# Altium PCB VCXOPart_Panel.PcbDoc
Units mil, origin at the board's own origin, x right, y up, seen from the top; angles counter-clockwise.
Board outline 8500 x 2950 mil, 4 copper layers (Top Layer, GND, VCC, Bottom Layer), stack 61.712 mil thick; 0 components, 0 nets, 52 pads, 0 vias.
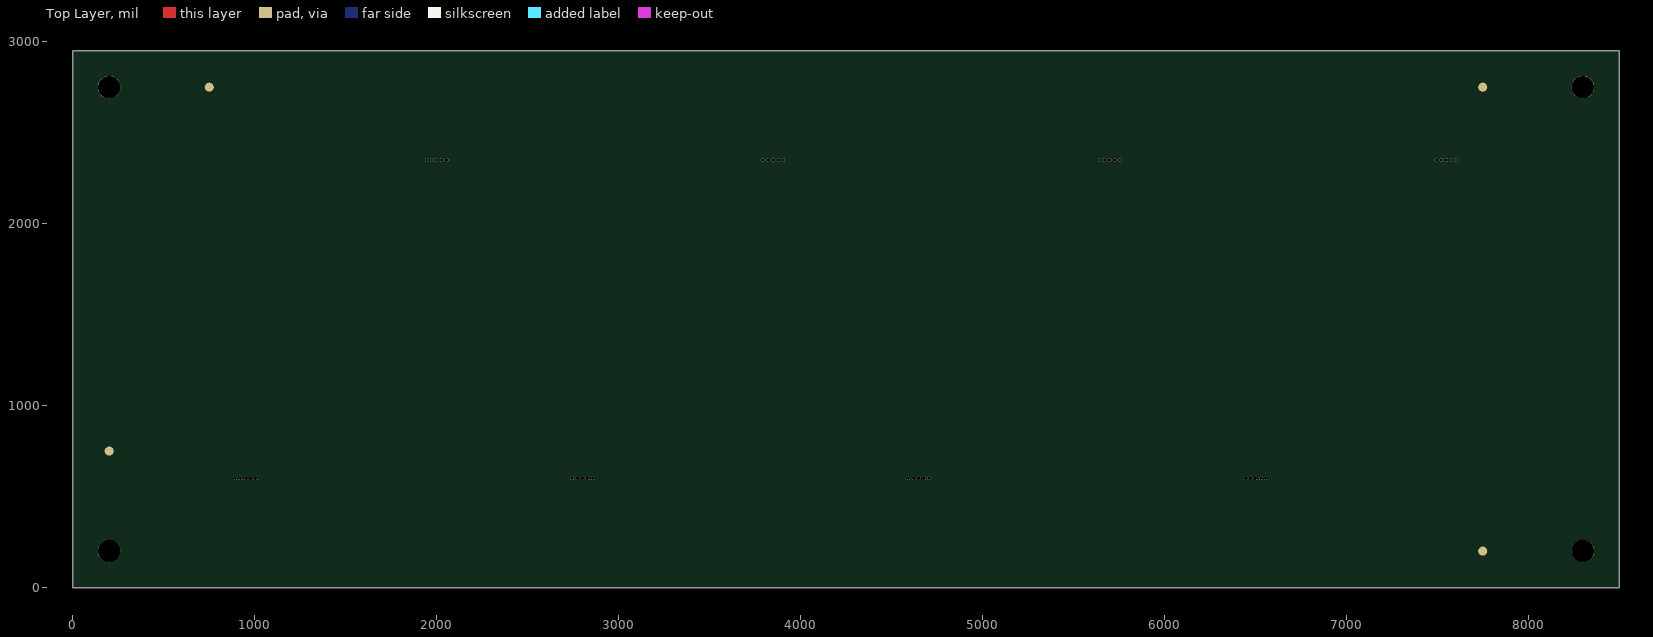
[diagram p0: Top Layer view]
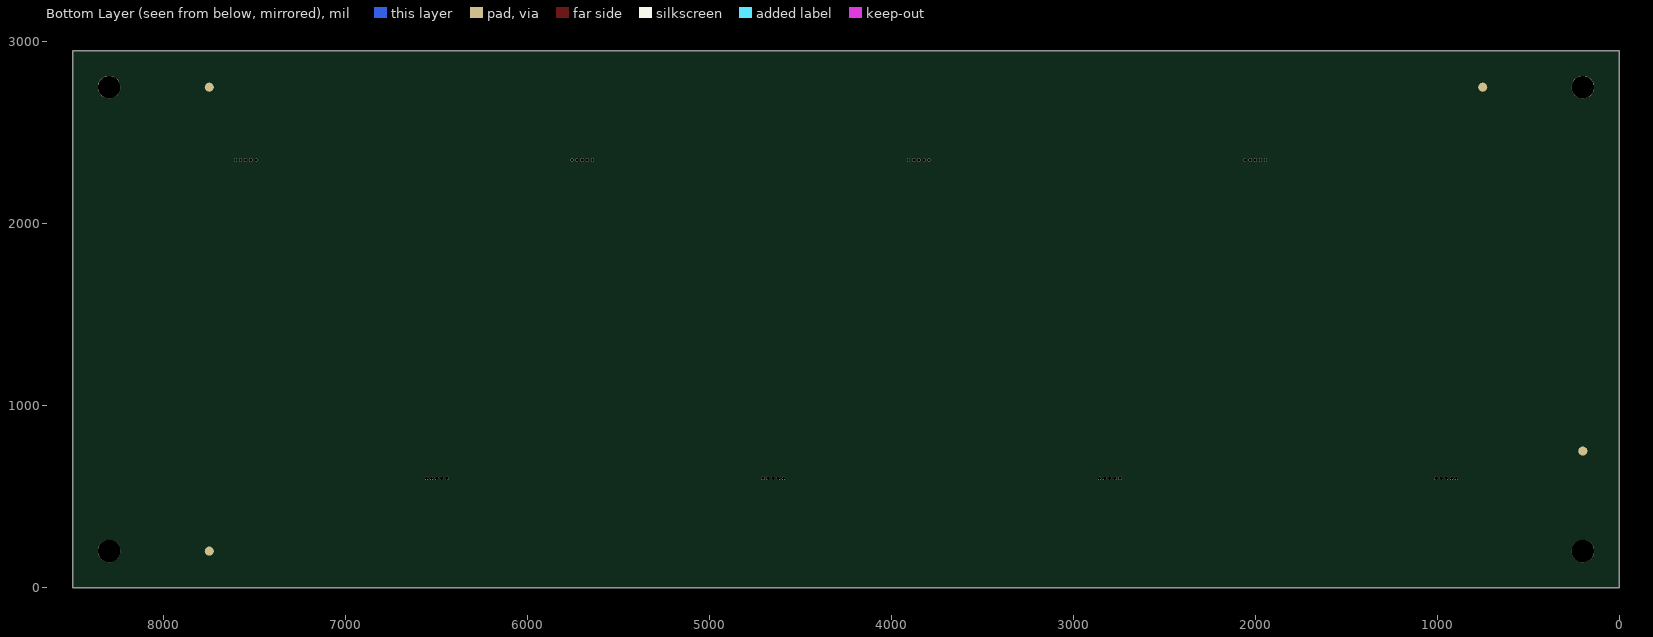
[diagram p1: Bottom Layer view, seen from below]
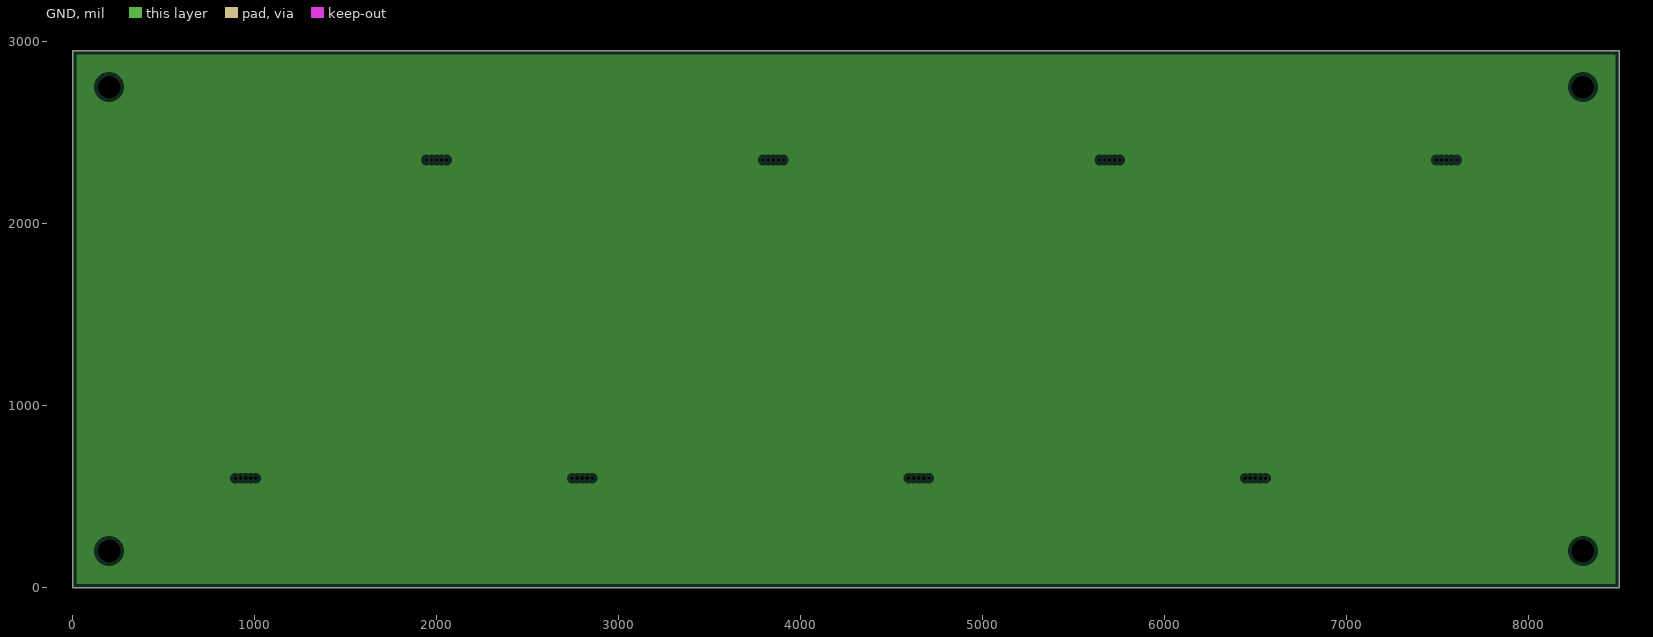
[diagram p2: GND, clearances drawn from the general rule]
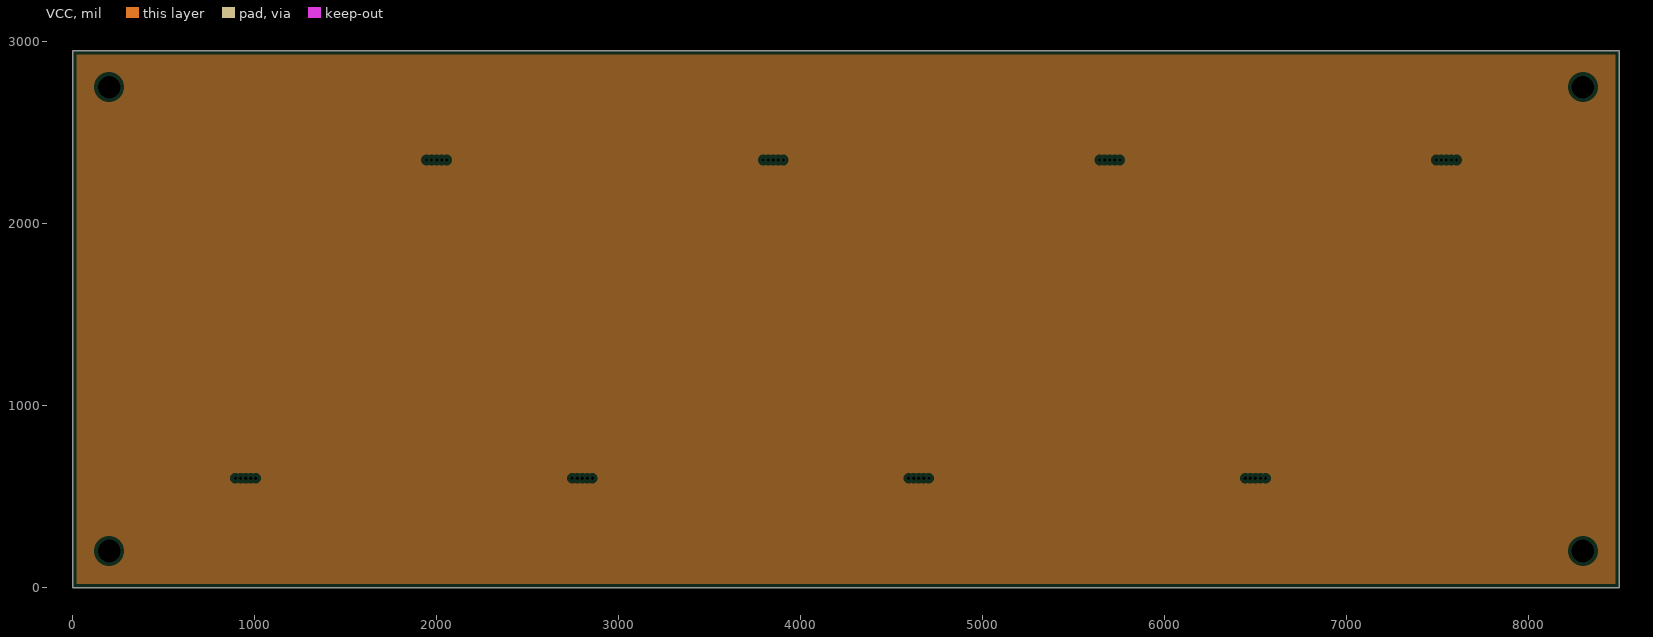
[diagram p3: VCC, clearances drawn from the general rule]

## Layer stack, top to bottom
Top Solder: solder mask 0.4, Solder Resist, Dk 3.5
Top Layer: signal copper 1.378
Dielectric 2: prepreg 8.6, 2116, 2113, Dk 4.3
GND: plane copper 1.378
Dielectric 1: core 39, FR-4, Dk 4.8
VCC: plane copper 1.378
Dielectric 3: prepreg 8.6, 2116, 2113, Dk 4.3
Bottom Layer: signal copper 1.378
Bottom Solder: solder mask 0.4, Solder Resist, Dk 3.5

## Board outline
0,0 0,2950 8500,2950 8500,0

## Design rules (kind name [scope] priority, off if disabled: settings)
Clearance [All] p1: gap=10 ignorepadtopadclearanceinfootprint=FALSE except(0: Arc-Hole Track-Hole SMDPad-Hole THPad-Hole Via-Hole Fill-Hole Poly-Hole Region-Hole Text-Hole)
PlaneClearance [All] p1: clearance=20
PlaneConnect [All] p1: planeconnectstyle=Relief reliefexpansion=20 reliefentries=4 reliefconductorwidth=10 reliefairgap=10
PolygonConnect [All] p1: connectstyle=Relief reliefconductorwidth=10 reliefentries=4 polygonreliefangle="90 Angle" airgapwidth=10
RoutingVias [All] p1: holewidth=28 width=50 viastyle="Through Hole" minholewidth=28 minwidth=50 maxholewidth=28 maxwidth=50
SolderMaskExpansion [All] p1: expansion=4 istentingtop=FALSE
Width [All] p1: maxlimit=10 minlimit=10 preferedwidth=10
28 further rules are at their usual default settings.

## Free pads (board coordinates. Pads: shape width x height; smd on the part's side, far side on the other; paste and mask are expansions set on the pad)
  round 125 hole 125 unplated: 0(200,200) 0(200,2750) 0(8300,200) 0(8300,2750)
  round 50 smd paste-50 mask+50: 0(200,750) 0(750,2750) 0(7750,200) 0(7750,2750)
  round 50 smd far side paste-50 mask+50: 0(200,750) 0(750,2750) 0(7750,200) 0(7750,2750)
  round 18 hole 18 unplated mask+0: 0(894,600) 0(922,600) 0(950,600) 0(978,600) 0(1006,600) 0(1944,2350) 0(1972,2350) 0(2000,2350) 0(2028,2350) 0(2056,2350) 0(2744,600) 0(2772,600) 0(2800,600) 0(2828,600) 0(2856,600) 0(3794,2350) 0(3822,2350) 0(3850,2350) 0(3878,2350) 0(3906,2350) 0(4594,600) 0(4622,600) 0(4650,600) 0(4678,600) 0(4706,600) 0(5644,2350) 0(5672,2350) 0(5700,2350) 0(5728,2350) 0(5756,2350) 0(6444,600) 0(6472,600) 0(6500,600) 0(6528,600) 0(6556,600) 0(7494,2350) 0(7522,2350) 0(7550,2350) 0(7578,2350) 0(7606,2350)

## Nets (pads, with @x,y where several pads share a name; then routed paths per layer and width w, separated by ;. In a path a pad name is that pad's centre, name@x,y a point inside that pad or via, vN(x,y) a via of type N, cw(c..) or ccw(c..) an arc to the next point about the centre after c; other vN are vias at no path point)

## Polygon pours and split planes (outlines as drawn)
no net on GND (split plane): 8479.9,20.1 20.1,20.1 20.1,2929.9 8479.9,2929.9
no net on VCC (split plane): 8479.9,20.1 20.1,20.1 20.1,2929.9 8479.9,2929.9

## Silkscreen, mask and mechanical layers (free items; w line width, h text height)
Mechanical 1:
  the board outline again, w8
Mechanical 2:
  lines w100: 850,550 550,550 550,1325 675,1325 675,1625 550,1625 550,2400 1325,2400 1325,2275 1625,2275 1625,2400 1900,2400 ; 1050,550 1325,550 1325,675 1625,675 1625,550 2700,550 ; 2100,2400 3175,2400 3175,2275 3475,2275 3475,2400 3750,2400 ; 2350,2350 2350,1625 2275,1625 2275,950 2400,950 ; 2400,600 2400,950 ; 2400,2350 2400,1625 2525,1625 2525,1325 2400,1325 2400,950 ; 2900,550 3175,550 3175,675 3475,675 3475,550 4550,550 ; 3950,2400 5025,2400 5025,2275 5325,2275 5325,2400 5600,2400 ; 4200,2350 4200,1625 4125,1625 4125,950 4250,950 ; 4250,600 4250,950 ; 4250,2350 4250,1625 4375,1625 4375,1325 4250,1325 4250,950 ; 4750,550 5025,550 5025,675 5325,675 5325,550 6400,550 ; 5800,2400 6850,2400 ; 6050,2350 6050,1625 5975,1625 5975,950 6100,950 ; 6100,600 6100,950 ; 6100,2350 6100,1625 6225,1625 6225,1325 6100,1325 6100,950 ; 6600,550 6875,550 6875,675 7175,675 7175,550 7950,550 7950,950 7825,950 7825,1625 7900,1625 7900,2400 7650,2400 ; 6875,2400 6875,2275 7175,2275 7175,2400 7450,2400
Mechanical 3:
  drawing of 212 lines, arcs and shapes, not listed
Drill Drawing:
  drawing of 473 lines, arcs and shapes, not listed
  text "Layer" at 70,7539.04 h60
  text "Name" at 479.91,7539.04 h60
  text "Material" at 1409.66,7539.04 h60
  text "Thickness" at 2269.42,7539.04 h60
  text "Constant" at 2919.26,7539.04 h60
  text "Board Layer Stack" at 3489.12,7539.04 h60
  text "Top Overlay" at 479.91,7419.04 h60
  text "Top Solder" at 479.91,7299.04 h60
  text "Solder Resist" at 1409.66,7299.04 h60
  text "0.40mil" at 2269.42,7299.04 h60
  text "3.5" at 2919.26,7299.04 h60
  text "1" at 70,7179.04 h60
  text "Top Layer" at 479.91,7179.04 h60
  text "CF-004" at 1409.66,7179.04 h60
  text "1.38mil" at 2269.42,7179.04 h60
  text "Dielectric 2" at 479.91,7059.04 h60
  text "2116, 2113" at 1409.66,7059.04 h60
  text "8.60mil" at 2269.42,7059.04 h60
  text "4.3" at 2919.26,7059.04 h60
  text "2" at 70,6939.04 h60
  text "GND" at 479.91,6939.04 h60
  text "CF-004" at 1409.66,6939.04 h60
  text "1.38mil" at 2269.42,6939.04 h60
  text "Dielectric 1" at 479.91,6819.04 h60
  text "FR-4" at 1409.66,6819.04 h60
  text "39.00mil" at 2269.42,6819.04 h60
  text "4.8" at 2919.26,6819.04 h60
  text "3" at 70,6699.04 h60
  text "VCC" at 479.91,6699.04 h60
  text "CF-004" at 1409.66,6699.04 h60
  text "1.38mil" at 2269.42,6699.04 h60
  text "Dielectric 3" at 479.91,6579.04 h60
  text "2116, 2113" at 1409.66,6579.04 h60
  text "8.60mil" at 2269.42,6579.04 h60
  text "4.3" at 2919.26,6579.04 h60
  text "4" at 70,6459.04 h60
  text "Bottom Layer" at 479.91,6459.04 h60
  text "CF-004" at 1409.66,6459.04 h60
  text "1.38mil" at 2269.42,6459.04 h60
  text "Bottom Solder" at 479.91,6339.04 h60
  text "Solder Resist" at 1409.66,6339.04 h60
  text "0.40mil" at 2269.42,6339.04 h60
  text "3.5" at 2919.26,6339.04 h60
  text "Bottom Overlay" at 479.91,6219.04 h60
  text "Symbol" at 97.5,4352.5 h72
  text "Count" at 603.38,4352.5 h72
  text "Hole Size" at 1203.22,4352.5 h72
  text "Plated" at 2342.88,4352.5 h72
  text "Hole Type" at 2848.76,4352.5 h72
  text "Drill Layer Pair" at 3582.56,4352.5 h72
  text "Via/Pad" at 5082.11,4352.5 h72
  text "Pad Shape" at 5671.96,4352.5 h72
  text "Template" at 6417.76,4352.5 h72
  text "Description" at 7787.35,4352.5 h72
  text "Hole Tolerance (+)" at 8641.11,4352.5 h72
  text "Hole Tolerance (-)" at 9974.72,4352.5 h72
  text "4" at 603.38,4202.5 h60
  text "45.00mil (1.143mm)" at 1203.22,4202.5 h60
  text "PTH" at 2342.88,4202.5 h60
  text "Round" at 2848.76,4202.5 h60
  text "Top Layer - Bottom Layer" at 3582.56,4202.5 h60
  text "Via" at 5082.11,4202.5 h60
  text "Rounded" at 5671.96,4202.5 h60
  text "v160h114m160_503323056" at 6417.76,4202.5 h60
  text "4" at 603.38,4052.5 h60
  text "125.00mil (3.175mm)" at 1203.22,4052.5 h60
  text "NPTH" at 2342.88,4052.5 h60
  text "Round" at 2848.76,4052.5 h60
  text "Top Layer - Bottom Layer" at 3582.56,4052.5 h60
  text "Pad" at 5082.11,4052.5 h60
  text "Rounded" at 5671.96,4052.5 h60
  text "c318hn318" at 6417.76,4052.5 h60
  text "8" at 603.38,3902.5 h60
  text "30.00mil (0.762mm)" at 1203.22,3902.5 h60
  text "PTH" at 2342.88,3902.5 h60
  text "Round" at 2848.76,3902.5 h60
  text "Top Layer - Bottom Layer" at 3582.56,3902.5 h60
  text "Pad" at 5082.11,3902.5 h60
  text "Rounded" at 5671.96,3902.5 h60
  text "c152h76" at 6417.76,3902.5 h60
  text "8" at 603.38,3752.5 h60
  text "125.00mil (3.175mm)" at 1203.22,3752.5 h60
  text "PTH" at 2342.88,3752.5 h60
  text "Round" at 2848.76,3752.5 h60
  text "Top Layer - Bottom Layer" at 3582.56,3752.5 h60
  text "Via" at 5082.11,3752.5 h60
  text "Rounded" at 5671.96,3752.5 h60
  text "(Mixed)" at 6417.76,3752.5 h60
  text "16" at 603.38,3602.5 h60
  text "62.21mil (1.580mm)" at 1203.22,3602.5 h60
  text "PTH" at 2342.88,3602.5 h60
  text "Round" at 2848.76,3602.5 h60
  text "Top Layer - Bottom Layer" at 3582.56,3602.5 h60
  text "Pad" at 5082.11,3602.5 h60
  text "Rounded" at 5671.96,3602.5 h60
  text "c254h158" at 6417.76,3602.5 h60
  text "40" at 603.38,3452.5 h60
  text "18.00mil (0.457mm)" at 1203.22,3452.5 h60
  text "NPTH" at 2342.88,3452.5 h60
  text "Round" at 2848.76,3452.5 h60
  text "Top Layer - Bottom Layer" at 3582.56,3452.5 h60
  text "Pad" at 5082.11,3452.5 h60
  text "Rounded" at 5671.96,3452.5 h60
  text "c46hn46m46" at 6417.76,3452.5 h60
  text "220" at 603.38,3302.5 h60
  text "13.00mil (0.330mm)" at 1203.22,3302.5 h60
  text "PTH" at 2342.88,3302.5 h60
  text "Round" at 2848.76,3302.5 h60
  text "Top Layer - Bottom Layer" at 3582.56,3302.5 h60
  text "Via" at 5082.11,3302.5 h60
  text "Rounded" at 5671.96,3302.5 h60
  text "(Mixed)" at 6417.76,3302.5 h60
  text "300 Total" at 603.38,3152.5 h60

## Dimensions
600,2350 to 0,2950 on Mechanical 1
600,600 to 2350,600 on Mechanical 1
600,2350 to 2450,2350 on Mechanical 1
600,600 to 600,2350 on Mechanical 1
600,600 to 0,0 on Mechanical 1
8500,2950 to 8500,0 on Mechanical 1
0,0 to 8500,0 on Mechanical 1

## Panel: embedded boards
"..\VCXOPart\VCXOPart.PcbDoc" at 600,600, 1 rows x 4 columns, spacing 1850 x 1850, rotation 0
